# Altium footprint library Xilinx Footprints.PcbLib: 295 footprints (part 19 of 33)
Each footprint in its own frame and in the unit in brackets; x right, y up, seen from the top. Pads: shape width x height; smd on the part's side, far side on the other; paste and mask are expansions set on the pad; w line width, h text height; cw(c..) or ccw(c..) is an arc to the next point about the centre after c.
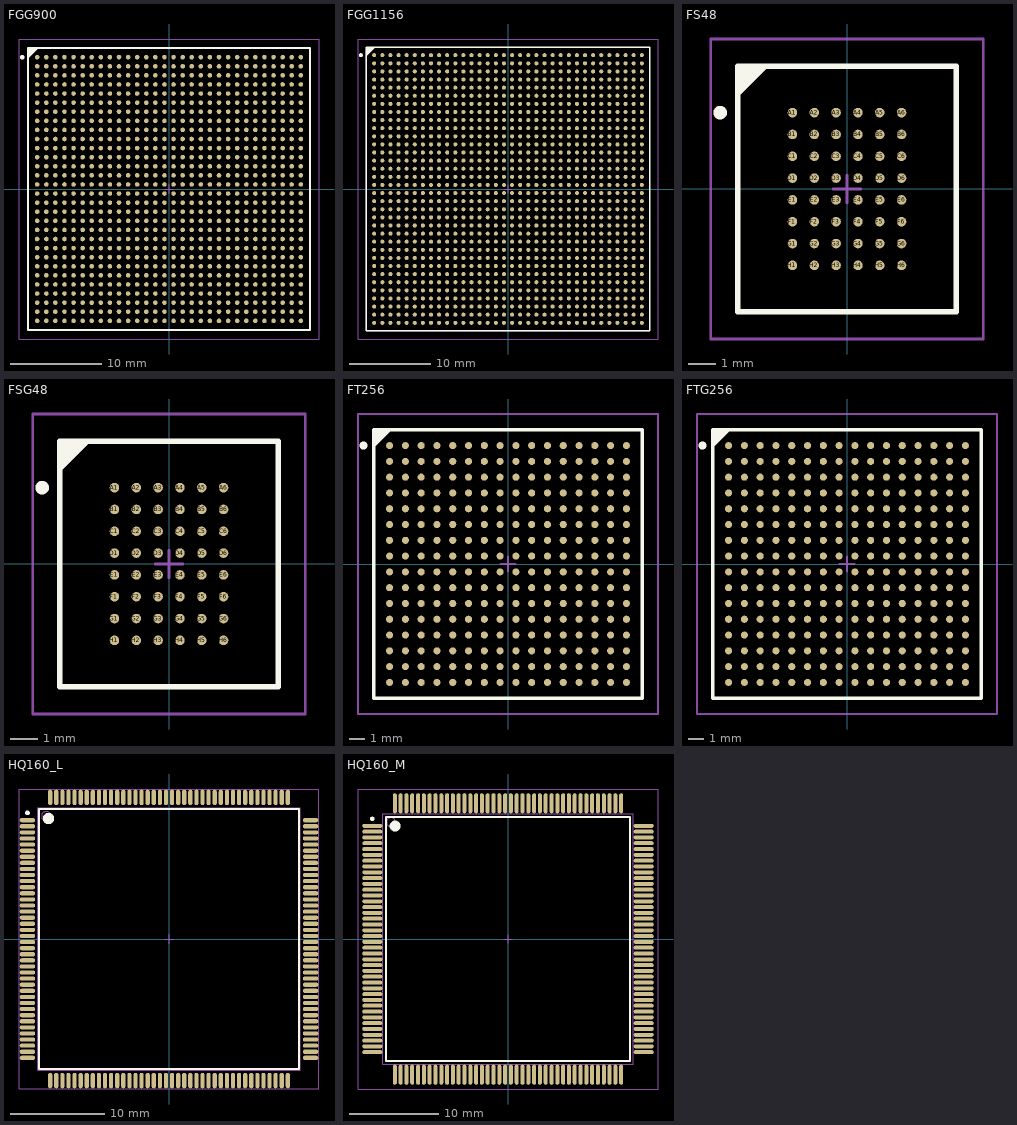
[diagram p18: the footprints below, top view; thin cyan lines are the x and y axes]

## FGG900 [mm] "900-Ball Fine Pitch Ball Grid Array (FGG900) - Pb-Free"
height 2.6
pads (900):
  round 0.5 smd: A1(-14.5,14.5) A2(-13.5,14.5) A3(-12.5,14.5) A4(-11.5,14.5) A5(-10.5,14.5) A6(-9.5,14.5) A7(-8.5,14.5) A8(-7.5,14.5) A9(-6.5,14.5) A10(-5.5,14.5) A11(-4.5,14.5) A12(-3.5,14.5) A13(-2.5,14.5) A14(-1.5,14.5) A15(-0.5,14.5) A16(0.5,14.5) A17(1.5,14.5) A18(2.5,14.5) A19(3.5,14.5) A20(4.5,14.5) A21(5.5,14.5) A22(6.5,14.5) A23(7.5,14.5) A24(8.5,14.5) A25(9.5,14.5) A26(10.5,14.5) A27(11.5,14.5) A28(12.5,14.5) A29(13.5,14.5) A30(14.5,14.5) AA1(-14.5,-5.5) AA2(-13.5,-5.5) AA3(-12.5,-5.5) AA4(-11.5,-5.5) AA5(-10.5,-5.5) AA6(-9.5,-5.5) AA7(-8.5,-5.5) AA8(-7.5,-5.5) AA9(-6.5,-5.5) AA10(-5.5,-5.5) AA11(-4.5,-5.5) AA12(-3.5,-5.5) AA13(-2.5,-5.5) AA14(-1.5,-5.5) AA15(-0.5,-5.5) AA16(0.5,-5.5) AA17(1.5,-5.5) AA18(2.5,-5.5) AA19(3.5,-5.5) AA20(4.5,-5.5) AA21(5.5,-5.5) AA22(6.5,-5.5) AA23(7.5,-5.5) AA24(8.5,-5.5) AA25(9.5,-5.5) AA26(10.5,-5.5) AA27(11.5,-5.5) AA28(12.5,-5.5) AA29(13.5,-5.5) AA30(14.5,-5.5) AB1(-14.5,-6.5) AB2(-13.5,-6.5) AB3(-12.5,-6.5) AB4(-11.5,-6.5) AB5(-10.5,-6.5) AB6(-9.5,-6.5) AB7(-8.5,-6.5) AB8(-7.5,-6.5) AB9(-6.5,-6.5) AB10(-5.5,-6.5) AB11(-4.5,-6.5) AB12(-3.5,-6.5) AB13(-2.5,-6.5) AB14(-1.5,-6.5) AB15(-0.5,-6.5) AB16(0.5,-6.5) AB17(1.5,-6.5) AB18(2.5,-6.5) AB19(3.5,-6.5) AB20(4.5,-6.5) AB21(5.5,-6.5) AB22(6.5,-6.5) AB23(7.5,-6.5) AB24(8.5,-6.5) AB25(9.5,-6.5) AB26(10.5,-6.5) AB27(11.5,-6.5) AB28(12.5,-6.5) AB29(13.5,-6.5) AB30(14.5,-6.5) AC1(-14.5,-7.5) AC2(-13.5,-7.5) AC3(-12.5,-7.5) AC4(-11.5,-7.5) AC5(-10.5,-7.5) AC6(-9.5,-7.5) AC7(-8.5,-7.5) AC8(-7.5,-7.5) AC9(-6.5,-7.5) AC10(-5.5,-7.5) AC11(-4.5,-7.5) AC12(-3.5,-7.5) AC13(-2.5,-7.5) AC14(-1.5,-7.5) AC15(-0.5,-7.5) AC16(0.5,-7.5) AC17(1.5,-7.5) AC18(2.5,-7.5) AC19(3.5,-7.5) AC20(4.5,-7.5) AC21(5.5,-7.5) AC22(6.5,-7.5) AC23(7.5,-7.5) AC24(8.5,-7.5) AC25(9.5,-7.5) AC26(10.5,-7.5) AC27(11.5,-7.5) AC28(12.5,-7.5) AC29(13.5,-7.5) AC30(14.5,-7.5) AD1(-14.5,-8.5) AD2(-13.5,-8.5) AD3(-12.5,-8.5) AD4(-11.5,-8.5) AD5(-10.5,-8.5) AD6(-9.5,-8.5) AD7(-8.5,-8.5) AD8(-7.5,-8.5) AD9(-6.5,-8.5) AD10(-5.5,-8.5) AD11(-4.5,-8.5) AD12(-3.5,-8.5) AD13(-2.5,-8.5) AD14(-1.5,-8.5) AD15(-0.5,-8.5) AD16(0.5,-8.5) AD17(1.5,-8.5) AD18(2.5,-8.5) AD19(3.5,-8.5) AD20(4.5,-8.5) AD21(5.5,-8.5) AD22(6.5,-8.5) AD23(7.5,-8.5) AD24(8.5,-8.5) AD25(9.5,-8.5) AD26(10.5,-8.5) AD27(11.5,-8.5) AD28(12.5,-8.5) AD29(13.5,-8.5) AD30(14.5,-8.5) AE1(-14.5,-9.5) AE2(-13.5,-9.5) AE3(-12.5,-9.5) AE4(-11.5,-9.5) AE5(-10.5,-9.5) AE6(-9.5,-9.5) AE7(-8.5,-9.5) AE8(-7.5,-9.5) AE9(-6.5,-9.5) AE10(-5.5,-9.5) AE11(-4.5,-9.5) AE12(-3.5,-9.5) AE13(-2.5,-9.5) AE14(-1.5,-9.5) AE15(-0.5,-9.5) AE16(0.5,-9.5) AE17(1.5,-9.5) AE18(2.5,-9.5) AE19(3.5,-9.5) AE20(4.5,-9.5) AE21(5.5,-9.5) AE22(6.5,-9.5) AE23(7.5,-9.5) AE24(8.5,-9.5) AE25(9.5,-9.5) AE26(10.5,-9.5) AE27(11.5,-9.5) AE28(12.5,-9.5) AE29(13.5,-9.5) AE30(14.5,-9.5) AF1(-14.5,-10.5) AF2(-13.5,-10.5) AF3(-12.5,-10.5) AF4(-11.5,-10.5) AF5(-10.5,-10.5) AF6(-9.5,-10.5) AF7(-8.5,-10.5) AF8(-7.5,-10.5) AF9(-6.5,-10.5) AF10(-5.5,-10.5) AF11(-4.5,-10.5) AF12(-3.5,-10.5) AF13(-2.5,-10.5) AF14(-1.5,-10.5) AF15(-0.5,-10.5) AF16(0.5,-10.5) AF17(1.5,-10.5) AF18(2.5,-10.5) AF19(3.5,-10.5) AF20(4.5,-10.5) AF21(5.5,-10.5) AF22(6.5,-10.5) AF23(7.5,-10.5) AF24(8.5,-10.5) AF25(9.5,-10.5) AF26(10.5,-10.5) AF27(11.5,-10.5) AF28(12.5,-10.5) AF29(13.5,-10.5) AF30(14.5,-10.5) AG1(-14.5,-11.5) AG2(-13.5,-11.5) AG3(-12.5,-11.5) AG4(-11.5,-11.5) AG5(-10.5,-11.5) AG6(-9.5,-11.5) AG7(-8.5,-11.5) AG8(-7.5,-11.5) AG9(-6.5,-11.5) AG10(-5.5,-11.5) AG11(-4.5,-11.5) AG12(-3.5,-11.5) AG13(-2.5,-11.5) AG14(-1.5,-11.5) AG15(-0.5,-11.5) AG16(0.5,-11.5) AG17(1.5,-11.5) AG18(2.5,-11.5) AG19(3.5,-11.5) AG20(4.5,-11.5) AG21(5.5,-11.5) AG22(6.5,-11.5) AG23(7.5,-11.5) AG24(8.5,-11.5) AG25(9.5,-11.5) AG26(10.5,-11.5) AG27(11.5,-11.5) AG28(12.5,-11.5) AG29(13.5,-11.5) AG30(14.5,-11.5) AH1(-14.5,-12.5) AH2(-13.5,-12.5) AH3(-12.5,-12.5) AH4(-11.5,-12.5) AH5(-10.5,-12.5) AH6(-9.5,-12.5) AH7(-8.5,-12.5) AH8(-7.5,-12.5) AH9(-6.5,-12.5) AH10(-5.5,-12.5) AH11(-4.5,-12.5) AH12(-3.5,-12.5) AH13(-2.5,-12.5) AH14(-1.5,-12.5) AH15(-0.5,-12.5) AH16(0.5,-12.5) AH17(1.5,-12.5) AH18(2.5,-12.5) AH19(3.5,-12.5) AH20(4.5,-12.5) AH21(5.5,-12.5) AH22(6.5,-12.5) AH23(7.5,-12.5) AH24(8.5,-12.5) AH25(9.5,-12.5) AH26(10.5,-12.5) AH27(11.5,-12.5) AH28(12.5,-12.5) AH29(13.5,-12.5) AH30(14.5,-12.5) AJ1(-14.5,-13.5) AJ2(-13.5,-13.5) AJ3(-12.5,-13.5) AJ4(-11.5,-13.5) AJ5(-10.5,-13.5) AJ6(-9.5,-13.5) AJ7(-8.5,-13.5) AJ8(-7.5,-13.5) AJ9(-6.5,-13.5) AJ10(-5.5,-13.5) AJ11(-4.5,-13.5) AJ12(-3.5,-13.5) AJ13(-2.5,-13.5) AJ14(-1.5,-13.5) AJ15(-0.5,-13.5) AJ16(0.5,-13.5) AJ17(1.5,-13.5) AJ18(2.5,-13.5) AJ19(3.5,-13.5) AJ20(4.5,-13.5) AJ21(5.5,-13.5) AJ22(6.5,-13.5) AJ23(7.5,-13.5) AJ24(8.5,-13.5) AJ25(9.5,-13.5) AJ26(10.5,-13.5) AJ27(11.5,-13.5) AJ28(12.5,-13.5) AJ29(13.5,-13.5) AJ30(14.5,-13.5) AK1(-14.5,-14.5) AK2(-13.5,-14.5) AK3(-12.5,-14.5) AK4(-11.5,-14.5) AK5(-10.5,-14.5) AK6(-9.5,-14.5) AK7(-8.5,-14.5) AK8(-7.5,-14.5) AK9(-6.5,-14.5) AK10(-5.5,-14.5) AK11(-4.5,-14.5) AK12(-3.5,-14.5) AK13(-2.5,-14.5) AK14(-1.5,-14.5) AK15(-0.5,-14.5) AK16(0.5,-14.5) AK17(1.5,-14.5) AK18(2.5,-14.5) AK19(3.5,-14.5) AK20(4.5,-14.5) AK21(5.5,-14.5) AK22(6.5,-14.5) AK23(7.5,-14.5) AK24(8.5,-14.5) AK25(9.5,-14.5) AK26(10.5,-14.5) AK27(11.5,-14.5) AK28(12.5,-14.5) AK29(13.5,-14.5) AK30(14.5,-14.5) B1(-14.5,13.5) B2(-13.5,13.5) B3(-12.5,13.5) B4(-11.5,13.5) B5(-10.5,13.5) B6(-9.5,13.5) B7(-8.5,13.5) B8(-7.5,13.5) B9(-6.5,13.5) B10(-5.5,13.5) B11(-4.5,13.5) B12(-3.5,13.5) B13(-2.5,13.5) B14(-1.5,13.5) B15(-0.5,13.5) B16(0.5,13.5) B17(1.5,13.5) B18(2.5,13.5) B19(3.5,13.5) B20(4.5,13.5) B21(5.5,13.5) B22(6.5,13.5) B23(7.5,13.5) B24(8.5,13.5) B25(9.5,13.5) B26(10.5,13.5) B27(11.5,13.5) B28(12.5,13.5) B29(13.5,13.5) B30(14.5,13.5) C1(-14.5,12.5) C2(-13.5,12.5) C3(-12.5,12.5) C4(-11.5,12.5) C5(-10.5,12.5) C6(-9.5,12.5) C7(-8.5,12.5) C8(-7.5,12.5) C9(-6.5,12.5) C10(-5.5,12.5) C11(-4.5,12.5) C12(-3.5,12.5) C13(-2.5,12.5) C14(-1.5,12.5) C15(-0.5,12.5) C16(0.5,12.5) C17(1.5,12.5) C18(2.5,12.5) C19(3.5,12.5) C20(4.5,12.5) C21(5.5,12.5) C22(6.5,12.5) C23(7.5,12.5) C24(8.5,12.5) C25(9.5,12.5) C26(10.5,12.5) C27(11.5,12.5) C28(12.5,12.5) C29(13.5,12.5) C30(14.5,12.5) D1(-14.5,11.5) D2(-13.5,11.5) D3(-12.5,11.5) D4(-11.5,11.5) D5(-10.5,11.5) D6(-9.5,11.5) D7(-8.5,11.5) D8(-7.5,11.5) D9(-6.5,11.5) D10(-5.5,11.5) D11(-4.5,11.5) D12(-3.5,11.5) D13(-2.5,11.5) D14(-1.5,11.5) D15(-0.5,11.5) D16(0.5,11.5) D17(1.5,11.5) D18(2.5,11.5) D19(3.5,11.5) D20(4.5,11.5) D21(5.5,11.5) D22(6.5,11.5) D23(7.5,11.5) D24(8.5,11.5) D25(9.5,11.5) D26(10.5,11.5) D27(11.5,11.5) D28(12.5,11.5) D29(13.5,11.5) D30(14.5,11.5) E1(-14.5,10.5) E2(-13.5,10.5) E3(-12.5,10.5) E4(-11.5,10.5) E5(-10.5,10.5) E6(-9.5,10.5) E7(-8.5,10.5) E8(-7.5,10.5) E9(-6.5,10.5) E10(-5.5,10.5) E11(-4.5,10.5) E12(-3.5,10.5) E13(-2.5,10.5) E14(-1.5,10.5) E15(-0.5,10.5) E16(0.5,10.5) E17(1.5,10.5) E18(2.5,10.5) E19(3.5,10.5) E20(4.5,10.5) E21(5.5,10.5) E22(6.5,10.5) E23(7.5,10.5) E24(8.5,10.5) E25(9.5,10.5) E26(10.5,10.5) E27(11.5,10.5) E28(12.5,10.5) E29(13.5,10.5) E30(14.5,10.5) F1(-14.5,9.5) F2(-13.5,9.5) F3(-12.5,9.5) F4(-11.5,9.5) F5(-10.5,9.5) F6(-9.5,9.5) F7(-8.5,9.5) F8(-7.5,9.5) F9(-6.5,9.5) F10(-5.5,9.5) F11(-4.5,9.5) F12(-3.5,9.5) F13(-2.5,9.5) F14(-1.5,9.5) F15(-0.5,9.5) F16(0.5,9.5) F17(1.5,9.5) F18(2.5,9.5) F19(3.5,9.5) F20(4.5,9.5) F21(5.5,9.5) F22(6.5,9.5) F23(7.5,9.5) F24(8.5,9.5) F25(9.5,9.5) F26(10.5,9.5) F27(11.5,9.5) F28(12.5,9.5) F29(13.5,9.5) F30(14.5,9.5) G1(-14.5,8.5) G2(-13.5,8.5) G3(-12.5,8.5) G4(-11.5,8.5) G5(-10.5,8.5) G6(-9.5,8.5) G7(-8.5,8.5) G8(-7.5,8.5) G9(-6.5,8.5) G10(-5.5,8.5) G11(-4.5,8.5) G12(-3.5,8.5) G13(-2.5,8.5) G14(-1.5,8.5) G15(-0.5,8.5) G16(0.5,8.5) G17(1.5,8.5) G18(2.5,8.5) G19(3.5,8.5) G20(4.5,8.5) G21(5.5,8.5) G22(6.5,8.5) G23(7.5,8.5) G24(8.5,8.5) G25(9.5,8.5) G26(10.5,8.5) G27(11.5,8.5) G28(12.5,8.5) G29(13.5,8.5) G30(14.5,8.5) H1(-14.5,7.5) H2(-13.5,7.5) H3(-12.5,7.5) H4(-11.5,7.5) H5(-10.5,7.5) H6(-9.5,7.5) H7(-8.5,7.5) H8(-7.5,7.5) H9(-6.5,7.5) H10(-5.5,7.5) H11(-4.5,7.5) H12(-3.5,7.5) H13(-2.5,7.5) H14(-1.5,7.5) H15(-0.5,7.5) H16(0.5,7.5) H17(1.5,7.5) H18(2.5,7.5) H19(3.5,7.5) H20(4.5,7.5) H21(5.5,7.5) H22(6.5,7.5) H23(7.5,7.5) H24(8.5,7.5) H25(9.5,7.5) H26(10.5,7.5) H27(11.5,7.5) H28(12.5,7.5) H29(13.5,7.5) H30(14.5,7.5) J1(-14.5,6.5) J2(-13.5,6.5) J3(-12.5,6.5) J4(-11.5,6.5) J5(-10.5,6.5) J6(-9.5,6.5) J7(-8.5,6.5) J8(-7.5,6.5) J9(-6.5,6.5) J10(-5.5,6.5) J11(-4.5,6.5) J12(-3.5,6.5) J13(-2.5,6.5) J14(-1.5,6.5) J15(-0.5,6.5) J16(0.5,6.5) J17(1.5,6.5) J18(2.5,6.5) J19(3.5,6.5) J20(4.5,6.5) J21(5.5,6.5) J22(6.5,6.5) J23(7.5,6.5) J24(8.5,6.5) J25(9.5,6.5) J26(10.5,6.5) J27(11.5,6.5) J28(12.5,6.5) J29(13.5,6.5) J30(14.5,6.5) K1(-14.5,5.5) K2(-13.5,5.5) K3(-12.5,5.5) K4(-11.5,5.5) K5(-10.5,5.5) K6(-9.5,5.5) K7(-8.5,5.5) K8(-7.5,5.5) K9(-6.5,5.5) K10(-5.5,5.5) K11(-4.5,5.5) K12(-3.5,5.5) K13(-2.5,5.5) K14(-1.5,5.5) K15(-0.5,5.5) K16(0.5,5.5) K17(1.5,5.5) K18(2.5,5.5) K19(3.5,5.5) K20(4.5,5.5) K21(5.5,5.5) K22(6.5,5.5) K23(7.5,5.5) K24(8.5,5.5) K25(9.5,5.5) K26(10.5,5.5) K27(11.5,5.5) K28(12.5,5.5) K29(13.5,5.5) K30(14.5,5.5) L1(-14.5,4.5) L2(-13.5,4.5) L3(-12.5,4.5) L4(-11.5,4.5) L5(-10.5,4.5) L6(-9.5,4.5) L7(-8.5,4.5) L8(-7.5,4.5) L9(-6.5,4.5) L10(-5.5,4.5) L11(-4.5,4.5) L12(-3.5,4.5) L13(-2.5,4.5) L14(-1.5,4.5) L15(-0.5,4.5) L16(0.5,4.5) L17(1.5,4.5) L18(2.5,4.5) L19(3.5,4.5) L20(4.5,4.5) L21(5.5,4.5) L22(6.5,4.5) L23(7.5,4.5) L24(8.5,4.5) L25(9.5,4.5) L26(10.5,4.5) L27(11.5,4.5) L28(12.5,4.5) L29(13.5,4.5) L30(14.5,4.5) M1(-14.5,3.5) M2(-13.5,3.5) M3(-12.5,3.5) M4(-11.5,3.5) M5(-10.5,3.5) M6(-9.5,3.5) M7(-8.5,3.5) M8(-7.5,3.5) M9(-6.5,3.5) M10(-5.5,3.5) M11(-4.5,3.5) M12(-3.5,3.5) M13(-2.5,3.5) M14(-1.5,3.5) M15(-0.5,3.5) M16(0.5,3.5) M17(1.5,3.5) M18(2.5,3.5) M19(3.5,3.5) M20(4.5,3.5) M21(5.5,3.5) M22(6.5,3.5) M23(7.5,3.5) M24(8.5,3.5) M25(9.5,3.5) M26(10.5,3.5) M27(11.5,3.5) M28(12.5,3.5) M29(13.5,3.5) M30(14.5,3.5) N1(-14.5,2.5) N2(-13.5,2.5) N3(-12.5,2.5) N4(-11.5,2.5) N5(-10.5,2.5) N6(-9.5,2.5) N7(-8.5,2.5) N8(-7.5,2.5) N9(-6.5,2.5) N10(-5.5,2.5) N11(-4.5,2.5) N12(-3.5,2.5) N13(-2.5,2.5) N14(-1.5,2.5) N15(-0.5,2.5) N16(0.5,2.5) N17(1.5,2.5) N18(2.5,2.5) N19(3.5,2.5) N20(4.5,2.5) N21(5.5,2.5) N22(6.5,2.5) N23(7.5,2.5) N24(8.5,2.5) N25(9.5,2.5) N26(10.5,2.5) N27(11.5,2.5) N28(12.5,2.5) N29(13.5,2.5) N30(14.5,2.5) P1(-14.5,1.5) P2(-13.5,1.5) P3(-12.5,1.5) P4(-11.5,1.5) P5(-10.5,1.5) P6(-9.5,1.5) P7(-8.5,1.5) P8(-7.5,1.5) P9(-6.5,1.5) P10(-5.5,1.5) P11(-4.5,1.5) P12(-3.5,1.5) P13(-2.5,1.5) P14(-1.5,1.5) P15(-0.5,1.5) P16(0.5,1.5) P17(1.5,1.5) P18(2.5,1.5) P19(3.5,1.5) P20(4.5,1.5) P21(5.5,1.5) P22(6.5,1.5) P23(7.5,1.5) P24(8.5,1.5) P25(9.5,1.5) P26(10.5,1.5) P27(11.5,1.5) P28(12.5,1.5) P29(13.5,1.5) P30(14.5,1.5) R1(-14.5,0.5) R2(-13.5,0.5) R3(-12.5,0.5) R4(-11.5,0.5) R5(-10.5,0.5) R6(-9.5,0.5) R7(-8.5,0.5) R8(-7.5,0.5) R9(-6.5,0.5) R10(-5.5,0.5) R11(-4.5,0.5) R12(-3.5,0.5) R13(-2.5,0.5) R14(-1.5,0.5) R15(-0.5,0.5) R16(0.5,0.5) R17(1.5,0.5) R18(2.5,0.5) R19(3.5,0.5) R20(4.5,0.5) R21(5.5,0.5) R22(6.5,0.5) R23(7.5,0.5) R24(8.5,0.5) R25(9.5,0.5) R26(10.5,0.5) R27(11.5,0.5) R28(12.5,0.5) R29(13.5,0.5) R30(14.5,0.5) T1(-14.5,-0.5) T2(-13.5,-0.5) T3(-12.5,-0.5) T4(-11.5,-0.5) T5(-10.5,-0.5) T6(-9.5,-0.5) T7(-8.5,-0.5) T8(-7.5,-0.5) T9(-6.5,-0.5) T10(-5.5,-0.5) T11(-4.5,-0.5) T12(-3.5,-0.5) T13(-2.5,-0.5) T14(-1.5,-0.5) T15(-0.5,-0.5) T16(0.5,-0.5) T17(1.5,-0.5) T18(2.5,-0.5) T19(3.5,-0.5) T20(4.5,-0.5) T21(5.5,-0.5) T22(6.5,-0.5) T23(7.5,-0.5) T24(8.5,-0.5) T25(9.5,-0.5) T26(10.5,-0.5) T27(11.5,-0.5) T28(12.5,-0.5) T29(13.5,-0.5) T30(14.5,-0.5) U1(-14.5,-1.5) U2(-13.5,-1.5) U3(-12.5,-1.5) U4(-11.5,-1.5) U5(-10.5,-1.5) U6(-9.5,-1.5) U7(-8.5,-1.5) U8(-7.5,-1.5) U9(-6.5,-1.5) U10(-5.5,-1.5) U11(-4.5,-1.5) U12(-3.5,-1.5) U13(-2.5,-1.5) U14(-1.5,-1.5) U15(-0.5,-1.5) U16(0.5,-1.5) U17(1.5,-1.5) U18(2.5,-1.5) U19(3.5,-1.5) U20(4.5,-1.5) U21(5.5,-1.5) U22(6.5,-1.5) U23(7.5,-1.5) U24(8.5,-1.5) U25(9.5,-1.5) U26(10.5,-1.5) U27(11.5,-1.5) U28(12.5,-1.5) U29(13.5,-1.5) U30(14.5,-1.5) V1(-14.5,-2.5) V2(-13.5,-2.5) V3(-12.5,-2.5) V4(-11.5,-2.5) V5(-10.5,-2.5) V6(-9.5,-2.5) V7(-8.5,-2.5) V8(-7.5,-2.5) V9(-6.5,-2.5) V10(-5.5,-2.5) V11(-4.5,-2.5) V12(-3.5,-2.5) V13(-2.5,-2.5) V14(-1.5,-2.5) V15(-0.5,-2.5) V16(0.5,-2.5) V17(1.5,-2.5) V18(2.5,-2.5) V19(3.5,-2.5) V20(4.5,-2.5) V21(5.5,-2.5) V22(6.5,-2.5) V23(7.5,-2.5) V24(8.5,-2.5) V25(9.5,-2.5) V26(10.5,-2.5) V27(11.5,-2.5) V28(12.5,-2.5) V29(13.5,-2.5) V30(14.5,-2.5) W1(-14.5,-3.5) W2(-13.5,-3.5) W3(-12.5,-3.5) W4(-11.5,-3.5) W5(-10.5,-3.5) W6(-9.5,-3.5) W7(-8.5,-3.5) W8(-7.5,-3.5) W9(-6.5,-3.5) W10(-5.5,-3.5) W11(-4.5,-3.5) W12(-3.5,-3.5) W13(-2.5,-3.5) W14(-1.5,-3.5) W15(-0.5,-3.5) W16(0.5,-3.5) W17(1.5,-3.5) W18(2.5,-3.5) W19(3.5,-3.5) W20(4.5,-3.5) W21(5.5,-3.5) W22(6.5,-3.5) W23(7.5,-3.5) W24(8.5,-3.5) W25(9.5,-3.5) W26(10.5,-3.5) W27(11.5,-3.5) W28(12.5,-3.5) W29(13.5,-3.5) W30(14.5,-3.5) Y1(-14.5,-4.5) Y2(-13.5,-4.5) Y3(-12.5,-4.5) Y4(-11.5,-4.5) Y5(-10.5,-4.5) Y6(-9.5,-4.5) Y7(-8.5,-4.5) Y8(-7.5,-4.5) Y9(-6.5,-4.5) Y10(-5.5,-4.5) Y11(-4.5,-4.5) Y12(-3.5,-4.5) Y13(-2.5,-4.5) Y14(-1.5,-4.5) Y15(-0.5,-4.5) Y16(0.5,-4.5) Y17(1.5,-4.5) Y18(2.5,-4.5) Y19(3.5,-4.5) Y20(4.5,-4.5) Y21(5.5,-4.5) Y22(6.5,-4.5) Y23(7.5,-4.5) Y24(8.5,-4.5) Y25(9.5,-4.5) Y26(10.5,-4.5) Y27(11.5,-4.5) Y28(12.5,-4.5) Y29(13.5,-4.5) Y30(14.5,-4.5)
Top Overlay:
  circle w0.25: c-16.15,14.5 r0.125
  region: -14.5,15.5 -15.5,14.5 -15.5,15.5
  lines w0.2: -15.5,14.5 -14.5,15.5 ; -15.5,-15.5 15.5,-15.5 15.5,15.5 -15.5,15.5 -15.5,-15.5
Mechanical 13:
  lines w0.1: -15.5,-15.5 15.5,-15.5 15.5,15.5 -15.5,15.5 -15.5,-15.5
Mechanical 15:
  lines w0.1: -0.5,0 0.5,0 ; 0,-0.5 0,0.5 ; -16.5,-16.5 16.5,-16.5 16.5,16.5 -16.5,16.5 -16.5,-16.5
3D body: height 2.6, standoff 0, extent -15.5,-15.5 15.5,15.5

## FGG1156 [mm] "1156-Ball Fine Pitch Plastic Ball Grid Array (FG1156) - Pb-Free"
height 2.6
pads (1156):
  round 0.5 smd: A1(-16.5,16.5) A2(-15.5,16.5) A3(-14.5,16.5) A4(-13.5,16.5) A5(-12.5,16.5) A6(-11.5,16.5) A7(-10.5,16.5) A8(-9.5,16.5) A9(-8.5,16.5) A10(-7.5,16.5) A11(-6.5,16.5) A12(-5.5,16.5) A13(-4.5,16.5) A14(-3.5,16.5) A15(-2.5,16.5) A16(-1.5,16.5) A17(-0.5,16.5) A18(0.5,16.5) A19(1.5,16.5) A20(2.5,16.5) A21(3.5,16.5) A22(4.5,16.5) A23(5.5,16.5) A24(6.5,16.5) A25(7.5,16.5) A26(8.5,16.5) A27(9.5,16.5) A28(10.5,16.5) A29(11.5,16.5) A30(12.5,16.5) A31(13.5,16.5) A32(14.5,16.5) A33(15.5,16.5) A34(16.5,16.5) AA1(-16.5,-3.5) AA2(-15.5,-3.5) AA3(-14.5,-3.5) AA4(-13.5,-3.5) AA5(-12.5,-3.5) AA6(-11.5,-3.5) AA7(-10.5,-3.5) AA8(-9.5,-3.5) AA9(-8.5,-3.5) AA10(-7.5,-3.5) AA11(-6.5,-3.5) AA12(-5.5,-3.5) AA13(-4.5,-3.5) AA14(-3.5,-3.5) AA15(-2.5,-3.5) AA16(-1.5,-3.5) AA17(-0.5,-3.5) AA18(0.5,-3.5) AA19(1.5,-3.5) AA20(2.5,-3.5) AA21(3.5,-3.5) AA22(4.5,-3.5) AA23(5.5,-3.5) AA24(6.5,-3.5) AA25(7.5,-3.5) AA26(8.5,-3.5) AA27(9.5,-3.5) AA28(10.5,-3.5) AA29(11.5,-3.5) AA30(12.5,-3.5) AA31(13.5,-3.5) AA32(14.5,-3.5) AA33(15.5,-3.5) AA34(16.5,-3.5) AB1(-16.5,-4.5) AB2(-15.5,-4.5) AB3(-14.5,-4.5) AB4(-13.5,-4.5) AB5(-12.5,-4.5) AB6(-11.5,-4.5) AB7(-10.5,-4.5) AB8(-9.5,-4.5) AB9(-8.5,-4.5) AB10(-7.5,-4.5) AB11(-6.5,-4.5) AB12(-5.5,-4.5) AB13(-4.5,-4.5) AB14(-3.5,-4.5) AB15(-2.5,-4.5) AB16(-1.5,-4.5) AB17(-0.5,-4.5) AB18(0.5,-4.5) AB19(1.5,-4.5) AB20(2.5,-4.5) AB21(3.5,-4.5) AB22(4.5,-4.5) AB23(5.5,-4.5) AB24(6.5,-4.5) AB25(7.5,-4.5) AB26(8.5,-4.5) AB27(9.5,-4.5) AB28(10.5,-4.5) AB29(11.5,-4.5) AB30(12.5,-4.5) AB31(13.5,-4.5) AB32(14.5,-4.5) AB33(15.5,-4.5) AB34(16.5,-4.5) AC1(-16.5,-5.5) AC2(-15.5,-5.5) AC3(-14.5,-5.5) AC4(-13.5,-5.5) AC5(-12.5,-5.5) AC6(-11.5,-5.5) AC7(-10.5,-5.5) AC8(-9.5,-5.5) AC9(-8.5,-5.5) AC10(-7.5,-5.5) AC11(-6.5,-5.5) AC12(-5.5,-5.5) AC13(-4.5,-5.5) AC14(-3.5,-5.5) AC15(-2.5,-5.5) AC16(-1.5,-5.5) AC17(-0.5,-5.5) AC18(0.5,-5.5) AC19(1.5,-5.5) AC20(2.5,-5.5) AC21(3.5,-5.5) AC22(4.5,-5.5) AC23(5.5,-5.5) AC24(6.5,-5.5) AC25(7.5,-5.5) AC26(8.5,-5.5) AC27(9.5,-5.5) AC28(10.5,-5.5) AC29(11.5,-5.5) AC30(12.5,-5.5) AC31(13.5,-5.5) AC32(14.5,-5.5) AC33(15.5,-5.5) AC34(16.5,-5.5) AD1(-16.5,-6.5) AD2(-15.5,-6.5) AD3(-14.5,-6.5) AD4(-13.5,-6.5) AD5(-12.5,-6.5) AD6(-11.5,-6.5) AD7(-10.5,-6.5) AD8(-9.5,-6.5) AD9(-8.5,-6.5) AD10(-7.5,-6.5) AD11(-6.5,-6.5) AD12(-5.5,-6.5) AD13(-4.5,-6.5) AD14(-3.5,-6.5) AD15(-2.5,-6.5) AD16(-1.5,-6.5) AD17(-0.5,-6.5) AD18(0.5,-6.5) AD19(1.5,-6.5) AD20(2.5,-6.5) AD21(3.5,-6.5) AD22(4.5,-6.5) AD23(5.5,-6.5) AD24(6.5,-6.5) AD25(7.5,-6.5) AD26(8.5,-6.5) AD27(9.5,-6.5) AD28(10.5,-6.5) AD29(11.5,-6.5) AD30(12.5,-6.5) AD31(13.5,-6.5) AD32(14.5,-6.5) AD33(15.5,-6.5) AD34(16.5,-6.5) AE1(-16.5,-7.5) AE2(-15.5,-7.5) AE3(-14.5,-7.5) AE4(-13.5,-7.5) AE5(-12.5,-7.5) AE6(-11.5,-7.5) AE7(-10.5,-7.5) AE8(-9.5,-7.5) AE9(-8.5,-7.5) AE10(-7.5,-7.5) AE11(-6.5,-7.5) AE12(-5.5,-7.5) AE13(-4.5,-7.5) AE14(-3.5,-7.5) AE15(-2.5,-7.5) AE16(-1.5,-7.5) AE17(-0.5,-7.5) AE18(0.5,-7.5) AE19(1.5,-7.5) AE20(2.5,-7.5) AE21(3.5,-7.5) AE22(4.5,-7.5) AE23(5.5,-7.5) AE24(6.5,-7.5) AE25(7.5,-7.5) AE26(8.5,-7.5) AE27(9.5,-7.5) AE28(10.5,-7.5) AE29(11.5,-7.5) AE30(12.5,-7.5) AE31(13.5,-7.5) AE32(14.5,-7.5) AE33(15.5,-7.5) AE34(16.5,-7.5) AF1(-16.5,-8.5) AF2(-15.5,-8.5) AF3(-14.5,-8.5) AF4(-13.5,-8.5) AF5(-12.5,-8.5) AF6(-11.5,-8.5) AF7(-10.5,-8.5) AF8(-9.5,-8.5) AF9(-8.5,-8.5) AF10(-7.5,-8.5) AF11(-6.5,-8.5) AF12(-5.5,-8.5) AF13(-4.5,-8.5) AF14(-3.5,-8.5) AF15(-2.5,-8.5) AF16(-1.5,-8.5) AF17(-0.5,-8.5) AF18(0.5,-8.5) AF19(1.5,-8.5) AF20(2.5,-8.5) AF21(3.5,-8.5) AF22(4.5,-8.5) AF23(5.5,-8.5) AF24(6.5,-8.5) AF25(7.5,-8.5) AF26(8.5,-8.5) AF27(9.5,-8.5) AF28(10.5,-8.5) AF29(11.5,-8.5) AF30(12.5,-8.5) AF31(13.5,-8.5) AF32(14.5,-8.5) AF33(15.5,-8.5) AF34(16.5,-8.5) AG1(-16.5,-9.5) AG2(-15.5,-9.5) AG3(-14.5,-9.5) AG4(-13.5,-9.5) AG5(-12.5,-9.5) AG6(-11.5,-9.5) AG7(-10.5,-9.5) AG8(-9.5,-9.5) AG9(-8.5,-9.5) AG10(-7.5,-9.5) AG11(-6.5,-9.5) AG12(-5.5,-9.5) AG13(-4.5,-9.5) AG14(-3.5,-9.5) AG15(-2.5,-9.5) AG16(-1.5,-9.5) AG17(-0.5,-9.5) AG18(0.5,-9.5) AG19(1.5,-9.5) AG20(2.5,-9.5) AG21(3.5,-9.5) AG22(4.5,-9.5) AG23(5.5,-9.5) AG24(6.5,-9.5) AG25(7.5,-9.5) AG26(8.5,-9.5) AG27(9.5,-9.5) AG28(10.5,-9.5) AG29(11.5,-9.5) AG30(12.5,-9.5) AG31(13.5,-9.5) AG32(14.5,-9.5) AG33(15.5,-9.5) AG34(16.5,-9.5) AH1(-16.5,-10.5) AH2(-15.5,-10.5) AH3(-14.5,-10.5) AH4(-13.5,-10.5) AH5(-12.5,-10.5) AH6(-11.5,-10.5) AH7(-10.5,-10.5) AH8(-9.5,-10.5) AH9(-8.5,-10.5) AH10(-7.5,-10.5) AH11(-6.5,-10.5) AH12(-5.5,-10.5) AH13(-4.5,-10.5) AH14(-3.5,-10.5) AH15(-2.5,-10.5) AH16(-1.5,-10.5) AH17(-0.5,-10.5) AH18(0.5,-10.5) AH19(1.5,-10.5) AH20(2.5,-10.5) AH21(3.5,-10.5) AH22(4.5,-10.5) AH23(5.5,-10.5) AH24(6.5,-10.5) AH25(7.5,-10.5) AH26(8.5,-10.5) AH27(9.5,-10.5) AH28(10.5,-10.5) AH29(11.5,-10.5) AH30(12.5,-10.5) AH31(13.5,-10.5) AH32(14.5,-10.5) AH33(15.5,-10.5) AH34(16.5,-10.5) AJ1(-16.5,-11.5) AJ2(-15.5,-11.5) AJ3(-14.5,-11.5) AJ4(-13.5,-11.5) AJ5(-12.5,-11.5) AJ6(-11.5,-11.5) AJ7(-10.5,-11.5) AJ8(-9.5,-11.5) AJ9(-8.5,-11.5) AJ10(-7.5,-11.5) AJ11(-6.5,-11.5) AJ12(-5.5,-11.5) AJ13(-4.5,-11.5) AJ14(-3.5,-11.5) AJ15(-2.5,-11.5) AJ16(-1.5,-11.5) AJ17(-0.5,-11.5) AJ18(0.5,-11.5) AJ19(1.5,-11.5) AJ20(2.5,-11.5) AJ21(3.5,-11.5) AJ22(4.5,-11.5) AJ23(5.5,-11.5) AJ24(6.5,-11.5) AJ25(7.5,-11.5) AJ26(8.5,-11.5) AJ27(9.5,-11.5) AJ28(10.5,-11.5) AJ29(11.5,-11.5) AJ30(12.5,-11.5) AJ31(13.5,-11.5) AJ32(14.5,-11.5) AJ33(15.5,-11.5) AJ34(16.5,-11.5) AK1(-16.5,-12.5) AK2(-15.5,-12.5) AK3(-14.5,-12.5) AK4(-13.5,-12.5) AK5(-12.5,-12.5) AK6(-11.5,-12.5) AK7(-10.5,-12.5) AK8(-9.5,-12.5) AK9(-8.5,-12.5) AK10(-7.5,-12.5) AK11(-6.5,-12.5) AK12(-5.5,-12.5) AK13(-4.5,-12.5) AK14(-3.5,-12.5) AK15(-2.5,-12.5) AK16(-1.5,-12.5) AK17(-0.5,-12.5) AK18(0.5,-12.5) AK19(1.5,-12.5) AK20(2.5,-12.5) AK21(3.5,-12.5) AK22(4.5,-12.5) AK23(5.5,-12.5) AK24(6.5,-12.5) AK25(7.5,-12.5) AK26(8.5,-12.5) AK27(9.5,-12.5) AK28(10.5,-12.5) AK29(11.5,-12.5) AK30(12.5,-12.5) AK31(13.5,-12.5) AK32(14.5,-12.5) AK33(15.5,-12.5) AK34(16.5,-12.5) AL1(-16.5,-13.5) AL2(-15.5,-13.5) AL3(-14.5,-13.5) AL4(-13.5,-13.5) AL5(-12.5,-13.5) AL6(-11.5,-13.5) AL7(-10.5,-13.5) AL8(-9.5,-13.5) AL9(-8.5,-13.5) AL10(-7.5,-13.5) AL11(-6.5,-13.5) AL12(-5.5,-13.5) AL13(-4.5,-13.5) AL14(-3.5,-13.5) AL15(-2.5,-13.5) AL16(-1.5,-13.5) AL17(-0.5,-13.5) AL18(0.5,-13.5) AL19(1.5,-13.5) AL20(2.5,-13.5) AL21(3.5,-13.5) AL22(4.5,-13.5) AL23(5.5,-13.5) AL24(6.5,-13.5) AL25(7.5,-13.5) AL26(8.5,-13.5) AL27(9.5,-13.5) AL28(10.5,-13.5) AL29(11.5,-13.5) AL30(12.5,-13.5) AL31(13.5,-13.5) AL32(14.5,-13.5) AL33(15.5,-13.5) AL34(16.5,-13.5) AM1(-16.5,-14.5) AM2(-15.5,-14.5) AM3(-14.5,-14.5) AM4(-13.5,-14.5) AM5(-12.5,-14.5) AM6(-11.5,-14.5) AM7(-10.5,-14.5) AM8(-9.5,-14.5) AM9(-8.5,-14.5) AM10(-7.5,-14.5) AM11(-6.5,-14.5) AM12(-5.5,-14.5) AM13(-4.5,-14.5) AM14(-3.5,-14.5) AM15(-2.5,-14.5) AM16(-1.5,-14.5) AM17(-0.5,-14.5) AM18(0.5,-14.5) AM19(1.5,-14.5) AM20(2.5,-14.5) AM21(3.5,-14.5) AM22(4.5,-14.5) AM23(5.5,-14.5) AM24(6.5,-14.5) AM25(7.5,-14.5) AM26(8.5,-14.5) AM27(9.5,-14.5) AM28(10.5,-14.5) AM29(11.5,-14.5) AM30(12.5,-14.5) AM31(13.5,-14.5) AM32(14.5,-14.5) AM33(15.5,-14.5) AM34(16.5,-14.5) AN1(-16.5,-15.5) AN2(-15.5,-15.5) AN3(-14.5,-15.5) AN4(-13.5,-15.5) AN5(-12.5,-15.5) AN6(-11.5,-15.5) AN7(-10.5,-15.5) AN8(-9.5,-15.5) AN9(-8.5,-15.5) AN10(-7.5,-15.5) AN11(-6.5,-15.5) AN12(-5.5,-15.5) AN13(-4.5,-15.5) AN14(-3.5,-15.5) AN15(-2.5,-15.5) AN16(-1.5,-15.5) AN17(-0.5,-15.5) AN18(0.5,-15.5) AN19(1.5,-15.5) AN20(2.5,-15.5) AN21(3.5,-15.5) AN22(4.5,-15.5) AN23(5.5,-15.5) AN24(6.5,-15.5) AN25(7.5,-15.5) AN26(8.5,-15.5) AN27(9.5,-15.5) AN28(10.5,-15.5) AN29(11.5,-15.5) AN30(12.5,-15.5) AN31(13.5,-15.5) AN32(14.5,-15.5) AN33(15.5,-15.5) AN34(16.5,-15.5) AP1(-16.5,-16.5) AP2(-15.5,-16.5) AP3(-14.5,-16.5) AP4(-13.5,-16.5) AP5(-12.5,-16.5) AP6(-11.5,-16.5) AP7(-10.5,-16.5) AP8(-9.5,-16.5) AP9(-8.5,-16.5) AP10(-7.5,-16.5) AP11(-6.5,-16.5) AP12(-5.5,-16.5) AP13(-4.5,-16.5) AP14(-3.5,-16.5) AP15(-2.5,-16.5) AP16(-1.5,-16.5) AP17(-0.5,-16.5) AP18(0.5,-16.5) AP19(1.5,-16.5) AP20(2.5,-16.5) AP21(3.5,-16.5) AP22(4.5,-16.5) AP23(5.5,-16.5) AP24(6.5,-16.5) AP25(7.5,-16.5) AP26(8.5,-16.5) AP27(9.5,-16.5) AP28(10.5,-16.5) AP29(11.5,-16.5) AP30(12.5,-16.5) AP31(13.5,-16.5) AP32(14.5,-16.5) AP33(15.5,-16.5) AP34(16.5,-16.5) B1(-16.5,15.5) B2(-15.5,15.5) B3(-14.5,15.5) B4(-13.5,15.5) B5(-12.5,15.5) B6(-11.5,15.5) B7(-10.5,15.5) B8(-9.5,15.5) B9(-8.5,15.5) B10(-7.5,15.5) B11(-6.5,15.5) B12(-5.5,15.5) B13(-4.5,15.5) B14(-3.5,15.5) B15(-2.5,15.5) B16(-1.5,15.5) B17(-0.5,15.5) B18(0.5,15.5) B19(1.5,15.5) B20(2.5,15.5) B21(3.5,15.5) B22(4.5,15.5) B23(5.5,15.5) B24(6.5,15.5) B25(7.5,15.5) B26(8.5,15.5) B27(9.5,15.5) B28(10.5,15.5) B29(11.5,15.5) B30(12.5,15.5) B31(13.5,15.5) B32(14.5,15.5) B33(15.5,15.5) B34(16.5,15.5) C1(-16.5,14.5) C2(-15.5,14.5) C3(-14.5,14.5) C4(-13.5,14.5) C5(-12.5,14.5) C6(-11.5,14.5) C7(-10.5,14.5) C8(-9.5,14.5) C9(-8.5,14.5) C10(-7.5,14.5) C11(-6.5,14.5) C12(-5.5,14.5) C13(-4.5,14.5) C14(-3.5,14.5) C15(-2.5,14.5) C16(-1.5,14.5) C17(-0.5,14.5) C18(0.5,14.5) C19(1.5,14.5) C20(2.5,14.5) C21(3.5,14.5) C22(4.5,14.5) C23(5.5,14.5) C24(6.5,14.5) C25(7.5,14.5) C26(8.5,14.5) C27(9.5,14.5) C28(10.5,14.5) C29(11.5,14.5) C30(12.5,14.5) C31(13.5,14.5) C32(14.5,14.5) C33(15.5,14.5) C34(16.5,14.5) D1(-16.5,13.5) D2(-15.5,13.5) D3(-14.5,13.5) D4(-13.5,13.5) D5(-12.5,13.5) D6(-11.5,13.5) D7(-10.5,13.5) D8(-9.5,13.5) D9(-8.5,13.5) D10(-7.5,13.5) D11(-6.5,13.5) D12(-5.5,13.5) D13(-4.5,13.5) D14(-3.5,13.5) D15(-2.5,13.5) D16(-1.5,13.5) D17(-0.5,13.5) D18(0.5,13.5) D19(1.5,13.5) D20(2.5,13.5) D21(3.5,13.5) D22(4.5,13.5) D23(5.5,13.5) D24(6.5,13.5) D25(7.5,13.5) D26(8.5,13.5) D27(9.5,13.5) D28(10.5,13.5) D29(11.5,13.5) D30(12.5,13.5) D31(13.5,13.5) D32(14.5,13.5) D33(15.5,13.5) D34(16.5,13.5) E1(-16.5,12.5) E2(-15.5,12.5) E3(-14.5,12.5) E4(-13.5,12.5) E5(-12.5,12.5) E6(-11.5,12.5) E7(-10.5,12.5) E8(-9.5,12.5) E9(-8.5,12.5) E10(-7.5,12.5) E11(-6.5,12.5) E12(-5.5,12.5) E13(-4.5,12.5) E14(-3.5,12.5) E15(-2.5,12.5) E16(-1.5,12.5) E17(-0.5,12.5) E18(0.5,12.5) E19(1.5,12.5) E20(2.5,12.5) E21(3.5,12.5) E22(4.5,12.5) E23(5.5,12.5) E24(6.5,12.5) E25(7.5,12.5) E26(8.5,12.5) E27(9.5,12.5) E28(10.5,12.5) E29(11.5,12.5) E30(12.5,12.5) E31(13.5,12.5) E32(14.5,12.5) E33(15.5,12.5) E34(16.5,12.5) F1(-16.5,11.5) F2(-15.5,11.5) F3(-14.5,11.5) F4(-13.5,11.5) F5(-12.5,11.5) F6(-11.5,11.5) F7(-10.5,11.5) F8(-9.5,11.5) F9(-8.5,11.5) F10(-7.5,11.5) F11(-6.5,11.5) F12(-5.5,11.5) F13(-4.5,11.5) F14(-3.5,11.5) F15(-2.5,11.5) F16(-1.5,11.5) F17(-0.5,11.5) F18(0.5,11.5) F19(1.5,11.5) F20(2.5,11.5) F21(3.5,11.5) F22(4.5,11.5) F23(5.5,11.5) F24(6.5,11.5) F25(7.5,11.5) F26(8.5,11.5) F27(9.5,11.5) F28(10.5,11.5) F29(11.5,11.5) F30(12.5,11.5) F31(13.5,11.5) F32(14.5,11.5) F33(15.5,11.5) F34(16.5,11.5) G1(-16.5,10.5) G2(-15.5,10.5) G3(-14.5,10.5) G4(-13.5,10.5) G5(-12.5,10.5) G6(-11.5,10.5) G7(-10.5,10.5) G8(-9.5,10.5) G9(-8.5,10.5) G10(-7.5,10.5) G11(-6.5,10.5) G12(-5.5,10.5) G13(-4.5,10.5) G14(-3.5,10.5) G15(-2.5,10.5) G16(-1.5,10.5) G17(-0.5,10.5) G18(0.5,10.5) G19(1.5,10.5) G20(2.5,10.5) G21(3.5,10.5) G22(4.5,10.5) G23(5.5,10.5) G24(6.5,10.5) G25(7.5,10.5) G26(8.5,10.5) G27(9.5,10.5) G28(10.5,10.5) G29(11.5,10.5) G30(12.5,10.5) G31(13.5,10.5) G32(14.5,10.5) G33(15.5,10.5) G34(16.5,10.5) H1(-16.5,9.5) H2(-15.5,9.5) H3(-14.5,9.5) H4(-13.5,9.5) H5(-12.5,9.5) H6(-11.5,9.5) H7(-10.5,9.5) H8(-9.5,9.5) H9(-8.5,9.5) H10(-7.5,9.5) H11(-6.5,9.5) H12(-5.5,9.5) H13(-4.5,9.5) H14(-3.5,9.5) H15(-2.5,9.5) H16(-1.5,9.5) H17(-0.5,9.5) H18(0.5,9.5) H19(1.5,9.5) H20(2.5,9.5) H21(3.5,9.5) H22(4.5,9.5) H23(5.5,9.5) H24(6.5,9.5) H25(7.5,9.5) H26(8.5,9.5) H27(9.5,9.5) H28(10.5,9.5) H29(11.5,9.5) H30(12.5,9.5) H31(13.5,9.5) H32(14.5,9.5) H33(15.5,9.5) H34(16.5,9.5) J1(-16.5,8.5) J2(-15.5,8.5) J3(-14.5,8.5) J4(-13.5,8.5) J5(-12.5,8.5) J6(-11.5,8.5) J7(-10.5,8.5) J8(-9.5,8.5) J9(-8.5,8.5) J10(-7.5,8.5) J11(-6.5,8.5) J12(-5.5,8.5) J13(-4.5,8.5) J14(-3.5,8.5) J15(-2.5,8.5) J16(-1.5,8.5) J17(-0.5,8.5) J18(0.5,8.5) J19(1.5,8.5) J20(2.5,8.5) J21(3.5,8.5) J22(4.5,8.5) J23(5.5,8.5) J24(6.5,8.5) J25(7.5,8.5) J26(8.5,8.5) J27(9.5,8.5) J28(10.5,8.5) J29(11.5,8.5) J30(12.5,8.5) J31(13.5,8.5) J32(14.5,8.5) J33(15.5,8.5) J34(16.5,8.5) K1(-16.5,7.5) K2(-15.5,7.5) K3(-14.5,7.5) K4(-13.5,7.5) K5(-12.5,7.5) K6(-11.5,7.5) K7(-10.5,7.5) K8(-9.5,7.5) K9(-8.5,7.5) K10(-7.5,7.5) K11(-6.5,7.5) K12(-5.5,7.5) K13(-4.5,7.5) K14(-3.5,7.5) K15(-2.5,7.5) K16(-1.5,7.5) K17(-0.5,7.5) K18(0.5,7.5) K19(1.5,7.5) K20(2.5,7.5) K21(3.5,7.5) K22(4.5,7.5) K23(5.5,7.5) K24(6.5,7.5) K25(7.5,7.5) K26(8.5,7.5) K27(9.5,7.5) K28(10.5,7.5) K29(11.5,7.5) K30(12.5,7.5) K31(13.5,7.5) K32(14.5,7.5) K33(15.5,7.5) K34(16.5,7.5) L1(-16.5,6.5) L2(-15.5,6.5) L3(-14.5,6.5) L4(-13.5,6.5) L5(-12.5,6.5) L6(-11.5,6.5) L7(-10.5,6.5) L8(-9.5,6.5) L9(-8.5,6.5) L10(-7.5,6.5) L11(-6.5,6.5) L12(-5.5,6.5) L13(-4.5,6.5) L14(-3.5,6.5) L15(-2.5,6.5) L16(-1.5,6.5) L17(-0.5,6.5) L18(0.5,6.5) L19(1.5,6.5) L20(2.5,6.5) L21(3.5,6.5) L22(4.5,6.5) L23(5.5,6.5) L24(6.5,6.5) L25(7.5,6.5) L26(8.5,6.5) L27(9.5,6.5) L28(10.5,6.5) L29(11.5,6.5) L30(12.5,6.5) L31(13.5,6.5) L32(14.5,6.5) L33(15.5,6.5) L34(16.5,6.5) M1(-16.5,5.5) M2(-15.5,5.5) M3(-14.5,5.5) M4(-13.5,5.5) M5(-12.5,5.5) M6(-11.5,5.5) M7(-10.5,5.5) M8(-9.5,5.5) M9(-8.5,5.5) M10(-7.5,5.5) M11(-6.5,5.5) M12(-5.5,5.5) M13(-4.5,5.5) M14(-3.5,5.5) M15(-2.5,5.5) M16(-1.5,5.5) M17(-0.5,5.5) M18(0.5,5.5) M19(1.5,5.5) M20(2.5,5.5) M21(3.5,5.5) M22(4.5,5.5) M23(5.5,5.5) M24(6.5,5.5) M25(7.5,5.5) M26(8.5,5.5) M27(9.5,5.5) M28(10.5,5.5) M29(11.5,5.5) M30(12.5,5.5) M31(13.5,5.5) M32(14.5,5.5) M33(15.5,5.5) M34(16.5,5.5) N1(-16.5,4.5) N2(-15.5,4.5) N3(-14.5,4.5) N4(-13.5,4.5) N5(-12.5,4.5) N6(-11.5,4.5) N7(-10.5,4.5) N8(-9.5,4.5) N9(-8.5,4.5) N10(-7.5,4.5) N11(-6.5,4.5) N12(-5.5,4.5) N13(-4.5,4.5) N14(-3.5,4.5) N15(-2.5,4.5) N16(-1.5,4.5) N17(-0.5,4.5) N18(0.5,4.5) N19(1.5,4.5) N20(2.5,4.5) N21(3.5,4.5) N22(4.5,4.5) N23(5.5,4.5) N24(6.5,4.5) N25(7.5,4.5) N26(8.5,4.5) N27(9.5,4.5) N28(10.5,4.5) N29(11.5,4.5) N30(12.5,4.5) N31(13.5,4.5) N32(14.5,4.5) N33(15.5,4.5) N34(16.5,4.5) P1(-16.5,3.5) P2(-15.5,3.5) P3(-14.5,3.5) P4(-13.5,3.5) P5(-12.5,3.5) P6(-11.5,3.5) P7(-10.5,3.5) P8(-9.5,3.5) P9(-8.5,3.5) P10(-7.5,3.5) P11(-6.5,3.5) P12(-5.5,3.5) P13(-4.5,3.5) P14(-3.5,3.5) P15(-2.5,3.5) P16(-1.5,3.5) P17(-0.5,3.5) P18(0.5,3.5) P19(1.5,3.5) P20(2.5,3.5) P21(3.5,3.5) P22(4.5,3.5) P23(5.5,3.5) P24(6.5,3.5) P25(7.5,3.5) P26(8.5,3.5) P27(9.5,3.5) P28(10.5,3.5) P29(11.5,3.5) P30(12.5,3.5) P31(13.5,3.5) P32(14.5,3.5) P33(15.5,3.5) P34(16.5,3.5) R1(-16.5,2.5) R2(-15.5,2.5) R3(-14.5,2.5) R4(-13.5,2.5) R5(-12.5,2.5) R6(-11.5,2.5) R7(-10.5,2.5) R8(-9.5,2.5) R9(-8.5,2.5) R10(-7.5,2.5) R11(-6.5,2.5) R12(-5.5,2.5) R13(-4.5,2.5) R14(-3.5,2.5) R15(-2.5,2.5) R16(-1.5,2.5) R17(-0.5,2.5) R18(0.5,2.5) R19(1.5,2.5) R20(2.5,2.5) R21(3.5,2.5) R22(4.5,2.5) R23(5.5,2.5) R24(6.5,2.5) R25(7.5,2.5) R26(8.5,2.5) R27(9.5,2.5) R28(10.5,2.5) R29(11.5,2.5) R30(12.5,2.5) R31(13.5,2.5) R32(14.5,2.5) R33(15.5,2.5) R34(16.5,2.5) T1(-16.5,1.5) T2(-15.5,1.5) T3(-14.5,1.5) T4(-13.5,1.5) T5(-12.5,1.5) T6(-11.5,1.5) T7(-10.5,1.5) T8(-9.5,1.5) T9(-8.5,1.5) T10(-7.5,1.5) T11(-6.5,1.5) T12(-5.5,1.5) T13(-4.5,1.5) T14(-3.5,1.5) T15(-2.5,1.5) T16(-1.5,1.5) T17(-0.5,1.5) T18(0.5,1.5) T19(1.5,1.5) T20(2.5,1.5) T21(3.5,1.5) T22(4.5,1.5) T23(5.5,1.5) T24(6.5,1.5) T25(7.5,1.5) T26(8.5,1.5) T27(9.5,1.5) T28(10.5,1.5) T29(11.5,1.5) T30(12.5,1.5) T31(13.5,1.5) T32(14.5,1.5) T33(15.5,1.5) T34(16.5,1.5) U1(-16.5,0.5) U2(-15.5,0.5) U3(-14.5,0.5) U4(-13.5,0.5) U5(-12.5,0.5) U6(-11.5,0.5) U7(-10.5,0.5) U8(-9.5,0.5) U9(-8.5,0.5) U10(-7.5,0.5) U11(-6.5,0.5) U12(-5.5,0.5) U13(-4.5,0.5) U14(-3.5,0.5) U15(-2.5,0.5) U16(-1.5,0.5) U17(-0.5,0.5) U18(0.5,0.5) U19(1.5,0.5) U20(2.5,0.5) U21(3.5,0.5) U22(4.5,0.5) U23(5.5,0.5) U24(6.5,0.5) U25(7.5,0.5) U26(8.5,0.5) U27(9.5,0.5) U28(10.5,0.5) U29(11.5,0.5) U30(12.5,0.5) U31(13.5,0.5) U32(14.5,0.5) U33(15.5,0.5) U34(16.5,0.5) V1(-16.5,-0.5) V2(-15.5,-0.5) V3(-14.5,-0.5) V4(-13.5,-0.5) V5(-12.5,-0.5) V6(-11.5,-0.5) V7(-10.5,-0.5) V8(-9.5,-0.5) V9(-8.5,-0.5) V10(-7.5,-0.5) V11(-6.5,-0.5) V12(-5.5,-0.5) V13(-4.5,-0.5) V14(-3.5,-0.5) V15(-2.5,-0.5) V16(-1.5,-0.5) V17(-0.5,-0.5) V18(0.5,-0.5) V19(1.5,-0.5) V20(2.5,-0.5) V21(3.5,-0.5) V22(4.5,-0.5) V23(5.5,-0.5) V24(6.5,-0.5) V25(7.5,-0.5) V26(8.5,-0.5) V27(9.5,-0.5) V28(10.5,-0.5) V29(11.5,-0.5) V30(12.5,-0.5) V31(13.5,-0.5) V32(14.5,-0.5) V33(15.5,-0.5) V34(16.5,-0.5) W1(-16.5,-1.5) W2(-15.5,-1.5) W3(-14.5,-1.5) W4(-13.5,-1.5) W5(-12.5,-1.5) W6(-11.5,-1.5) W7(-10.5,-1.5) W8(-9.5,-1.5) W9(-8.5,-1.5) W10(-7.5,-1.5) W11(-6.5,-1.5) W12(-5.5,-1.5) W13(-4.5,-1.5) W14(-3.5,-1.5) W15(-2.5,-1.5) W16(-1.5,-1.5) W17(-0.5,-1.5) W18(0.5,-1.5) W19(1.5,-1.5) W20(2.5,-1.5) W21(3.5,-1.5) W22(4.5,-1.5) W23(5.5,-1.5) W24(6.5,-1.5) W25(7.5,-1.5) W26(8.5,-1.5) W27(9.5,-1.5) W28(10.5,-1.5) W29(11.5,-1.5) W30(12.5,-1.5) W31(13.5,-1.5) W32(14.5,-1.5) W33(15.5,-1.5) W34(16.5,-1.5) Y1(-16.5,-2.5) Y2(-15.5,-2.5) Y3(-14.5,-2.5) Y4(-13.5,-2.5) Y5(-12.5,-2.5) Y6(-11.5,-2.5) Y7(-10.5,-2.5) Y8(-9.5,-2.5) Y9(-8.5,-2.5) Y10(-7.5,-2.5) Y11(-6.5,-2.5) Y12(-5.5,-2.5) Y13(-4.5,-2.5) Y14(-3.5,-2.5) Y15(-2.5,-2.5) Y16(-1.5,-2.5) Y17(-0.5,-2.5) Y18(0.5,-2.5) Y19(1.5,-2.5) Y20(2.5,-2.5) Y21(3.5,-2.5) Y22(4.5,-2.5) Y23(5.5,-2.5) Y24(6.5,-2.5) Y25(7.5,-2.5) Y26(8.5,-2.5) Y27(9.5,-2.5) Y28(10.5,-2.5) Y29(11.5,-2.5) Y30(12.5,-2.5) Y31(13.5,-2.5) Y32(14.5,-2.5) Y33(15.5,-2.5) Y34(16.5,-2.5)
Top Overlay:
  circle w0.25: c-18.15,16.5 r0.125
  region: -16.5,17.5 -17.5,16.5 -17.5,17.5
  lines w0.2: -17.5,16.5 -16.5,17.5 ; -17.5,-17.5 -17.5,17.5 17.5,17.5 17.5,-17.5 -17.5,-17.5
Mechanical 13:
  lines w0.1: -17.5,-17.5 -17.5,17.5 17.5,17.5 17.5,-17.5 -17.5,-17.5
Mechanical 15:
  lines w0.1: -0.5,0 0.5,0 ; 0,-0.5 0,0.5 ; -18.5,-18.5 -18.5,18.5 18.5,18.5 18.5,-18.5 -18.5,-18.5
3D body: height 2.6, standoff 0, extent -17.5,-17.5 17.5,17.5

## FS48 [mm] "48-Ball Chip Scale Ball Grid Array 0.8 mm Pitch (FS48)"
height 1.2
pads (48):
  round 0.35 smd: A1(-2,2.8) A2(-1.2,2.8) A3(-0.4,2.8) A4(0.4,2.8) A5(1.2,2.8) A6(2,2.8) B1(-2,2) B2(-1.2,2) B3(-0.4,2) B4(0.4,2) B5(1.2,2) B6(2,2) C1(-2,1.2) C2(-1.2,1.2) C3(-0.4,1.2) C4(0.4,1.2) C5(1.2,1.2) C6(2,1.2) D1(-2,0.4) D2(-1.2,0.4) D3(-0.4,0.4) D4(0.4,0.4) D5(1.2,0.4) D6(2,0.4) E1(-2,-0.4) E2(-1.2,-0.4) E3(-0.4,-0.4) E4(0.4,-0.4) E5(1.2,-0.4) E6(2,-0.4) F1(-2,-1.2) F2(-1.2,-1.2) F3(-0.4,-1.2) F4(0.4,-1.2) F5(1.2,-1.2) F6(2,-1.2) G1(-2,-2) G2(-1.2,-2) G3(-0.4,-2) G4(0.4,-2) G5(1.2,-2) G6(2,-2) H1(-2,-2.8) H2(-1.2,-2.8) H3(-0.4,-2.8) H4(0.4,-2.8) H5(1.2,-2.8) H6(2,-2.8)
Top Overlay:
  circle w0.25: c-4.65,2.8 r0.125
  region: -3,4.5 -4,3.5 -4,4.5
  lines w0.2: -4,3.5 -3,4.5 ; -4,-4.5 -4,4.5 4,4.5 4,-4.5 -4,-4.5
Mechanical 13:
  lines w0.1: -4,-4.5 -4,4.5 4,4.5 4,-4.5 -4,-4.5
Mechanical 15:
  lines w0.1: -0.5,0 0.5,0 ; 0,-0.5 0,0.5 ; -5,-5.5 -5,5.5 5,5.5 5,-5.5 -5,-5.5
3D body: height 1.2, standoff 0, extent -4,-4.5 4,4.5

## FSG48 [mm] "48-Ball Chip Scale Ball Grid Array 0.8 mm Pitch (FSG48) - Pb-Free"
height 1.2
pads (48):
  round 0.35 smd: A1(-2,2.8) A2(-1.2,2.8) A3(-0.4,2.8) A4(0.4,2.8) A5(1.2,2.8) A6(2,2.8) B1(-2,2) B2(-1.2,2) B3(-0.4,2) B4(0.4,2) B5(1.2,2) B6(2,2) C1(-2,1.2) C2(-1.2,1.2) C3(-0.4,1.2) C4(0.4,1.2) C5(1.2,1.2) C6(2,1.2) D1(-2,0.4) D2(-1.2,0.4) D3(-0.4,0.4) D4(0.4,0.4) D5(1.2,0.4) D6(2,0.4) E1(-2,-0.4) E2(-1.2,-0.4) E3(-0.4,-0.4) E4(0.4,-0.4) E5(1.2,-0.4) E6(2,-0.4) F1(-2,-1.2) F2(-1.2,-1.2) F3(-0.4,-1.2) F4(0.4,-1.2) F5(1.2,-1.2) F6(2,-1.2) G1(-2,-2) G2(-1.2,-2) G3(-0.4,-2) G4(0.4,-2) G5(1.2,-2) G6(2,-2) H1(-2,-2.8) H2(-1.2,-2.8) H3(-0.4,-2.8) H4(0.4,-2.8) H5(1.2,-2.8) H6(2,-2.8)
Top Overlay:
  circle w0.25: c-4.65,2.8 r0.125
  region: -3,4.5 -4,3.5 -4,4.5
  lines w0.2: -4,3.5 -3,4.5 ; -4,-4.5 4,-4.5 4,4.5 -4,4.5 -4,-4.5
Mechanical 13:
  lines w0.1: -4,-4.5 4,-4.5 4,4.5 -4,4.5 -4,-4.5
Mechanical 15:
  lines w0.1: -0.5,0 0.5,0 ; 0,-0.5 0,0.5 ; -5,-5.5 5,-5.5 5,5.5 -5,5.5 -5,-5.5
3D body: height 1.2, standoff 0, extent -4,-4.5 4,4.5

## FT256 [mm] "256-Ball Fine Pitch Thin Ball Grid Array 1.00 mm Pitch (FT256)"
height 1.55
pads (256):
  round 0.45 smd: A1(-7.5,7.5) A2(-6.5,7.5) A3(-5.5,7.5) A4(-4.5,7.5) A5(-3.5,7.5) A6(-2.5,7.5) A7(-1.5,7.5) A8(-0.5,7.5) A9(0.5,7.5) A10(1.5,7.5) A11(2.5,7.5) A12(3.5,7.5) A13(4.5,7.5) A14(5.5,7.5) A15(6.5,7.5) A16(7.5,7.5) B1(-7.5,6.5) B2(-6.5,6.5) B3(-5.5,6.5) B4(-4.5,6.5) B5(-3.5,6.5) B6(-2.5,6.5) B7(-1.5,6.5) B8(-0.5,6.5) B9(0.5,6.5) B10(1.5,6.5) B11(2.5,6.5) B12(3.5,6.5) B13(4.5,6.5) B14(5.5,6.5) B15(6.5,6.5) B16(7.5,6.5) C1(-7.5,5.5) C2(-6.5,5.5) C3(-5.5,5.5) C4(-4.5,5.5) C5(-3.5,5.5) C6(-2.5,5.5) C7(-1.5,5.5) C8(-0.5,5.5) C9(0.5,5.5) C10(1.5,5.5) C11(2.5,5.5) C12(3.5,5.5) C13(4.5,5.5) C14(5.5,5.5) C15(6.5,5.5) C16(7.5,5.5) D1(-7.5,4.5) D2(-6.5,4.5) D3(-5.5,4.5) D4(-4.5,4.5) D5(-3.5,4.5) D6(-2.5,4.5) D7(-1.5,4.5) D8(-0.5,4.5) D9(0.5,4.5) D10(1.5,4.5) D11(2.5,4.5) D12(3.5,4.5) D13(4.5,4.5) D14(5.5,4.5) D15(6.5,4.5) D16(7.5,4.5) E1(-7.5,3.5) E2(-6.5,3.5) E3(-5.5,3.5) E4(-4.5,3.5) E5(-3.5,3.5) E6(-2.5,3.5) E7(-1.5,3.5) E8(-0.5,3.5) E9(0.5,3.5) E10(1.5,3.5) E11(2.5,3.5) E12(3.5,3.5) E13(4.5,3.5) E14(5.5,3.5) E15(6.5,3.5) E16(7.5,3.5) F1(-7.5,2.5) F2(-6.5,2.5) F3(-5.5,2.5) F4(-4.5,2.5) F5(-3.5,2.5) F6(-2.5,2.5) F7(-1.5,2.5) F8(-0.5,2.5) F9(0.5,2.5) F10(1.5,2.5) F11(2.5,2.5) F12(3.5,2.5) F13(4.5,2.5) F14(5.5,2.5) F15(6.5,2.5) F16(7.5,2.5) G1(-7.5,1.5) G2(-6.5,1.5) G3(-5.5,1.5) G4(-4.5,1.5) G5(-3.5,1.5) G6(-2.5,1.5) G7(-1.5,1.5) G8(-0.5,1.5) G9(0.5,1.5) G10(1.5,1.5) G11(2.5,1.5) G12(3.5,1.5) G13(4.5,1.5) G14(5.5,1.5) G15(6.5,1.5) G16(7.5,1.5) H1(-7.5,0.5) H2(-6.5,0.5) H3(-5.5,0.5) H4(-4.5,0.5) H5(-3.5,0.5) H6(-2.5,0.5) H7(-1.5,0.5) H8(-0.5,0.5) H9(0.5,0.5) H10(1.5,0.5) H11(2.5,0.5) H12(3.5,0.5) H13(4.5,0.5) H14(5.5,0.5) H15(6.5,0.5) H16(7.5,0.5) J1(-7.5,-0.5) J2(-6.5,-0.5) J3(-5.5,-0.5) J4(-4.5,-0.5) J5(-3.5,-0.5) J6(-2.5,-0.5) J7(-1.5,-0.5) J8(-0.5,-0.5) J9(0.5,-0.5) J10(1.5,-0.5) J11(2.5,-0.5) J12(3.5,-0.5) J13(4.5,-0.5) J14(5.5,-0.5) J15(6.5,-0.5) J16(7.5,-0.5) K1(-7.5,-1.5) K2(-6.5,-1.5) K3(-5.5,-1.5) K4(-4.5,-1.5) K5(-3.5,-1.5) K6(-2.5,-1.5) K7(-1.5,-1.5) K8(-0.5,-1.5) K9(0.5,-1.5) K10(1.5,-1.5) K11(2.5,-1.5) K12(3.5,-1.5) K13(4.5,-1.5) K14(5.5,-1.5) K15(6.5,-1.5) K16(7.5,-1.5) L1(-7.5,-2.5) L2(-6.5,-2.5) L3(-5.5,-2.5) L4(-4.5,-2.5) L5(-3.5,-2.5) L6(-2.5,-2.5) L7(-1.5,-2.5) L8(-0.5,-2.5) L9(0.5,-2.5) L10(1.5,-2.5) L11(2.5,-2.5) L12(3.5,-2.5) L13(4.5,-2.5) L14(5.5,-2.5) L15(6.5,-2.5) L16(7.5,-2.5) M1(-7.5,-3.5) M2(-6.5,-3.5) M3(-5.5,-3.5) M4(-4.5,-3.5) M5(-3.5,-3.5) M6(-2.5,-3.5) M7(-1.5,-3.5) M8(-0.5,-3.5) M9(0.5,-3.5) M10(1.5,-3.5) M11(2.5,-3.5) M12(3.5,-3.5) M13(4.5,-3.5) M14(5.5,-3.5) M15(6.5,-3.5) M16(7.5,-3.5) N1(-7.5,-4.5) N2(-6.5,-4.5) N3(-5.5,-4.5) N4(-4.5,-4.5) N5(-3.5,-4.5) N6(-2.5,-4.5) N7(-1.5,-4.5) N8(-0.5,-4.5) N9(0.5,-4.5) N10(1.5,-4.5) N11(2.5,-4.5) N12(3.5,-4.5) N13(4.5,-4.5) N14(5.5,-4.5) N15(6.5,-4.5) N16(7.5,-4.5) P1(-7.5,-5.5) P2(-6.5,-5.5) P3(-5.5,-5.5) P4(-4.5,-5.5) P5(-3.5,-5.5) P6(-2.5,-5.5) P7(-1.5,-5.5) P8(-0.5,-5.5) P9(0.5,-5.5) P10(1.5,-5.5) P11(2.5,-5.5) P12(3.5,-5.5) P13(4.5,-5.5) P14(5.5,-5.5) P15(6.5,-5.5) P16(7.5,-5.5) R1(-7.5,-6.5) R2(-6.5,-6.5) R3(-5.5,-6.5) R4(-4.5,-6.5) R5(-3.5,-6.5) R6(-2.5,-6.5) R7(-1.5,-6.5) R8(-0.5,-6.5) R9(0.5,-6.5) R10(1.5,-6.5) R11(2.5,-6.5) R12(3.5,-6.5) R13(4.5,-6.5) R14(5.5,-6.5) R15(6.5,-6.5) R16(7.5,-6.5) T1(-7.5,-7.5) T2(-6.5,-7.5) T3(-5.5,-7.5) T4(-4.5,-7.5) T5(-3.5,-7.5) T6(-2.5,-7.5) T7(-1.5,-7.5) T8(-0.5,-7.5) T9(0.5,-7.5) T10(1.5,-7.5) T11(2.5,-7.5) T12(3.5,-7.5) T13(4.5,-7.5) T14(5.5,-7.5) T15(6.5,-7.5) T16(7.5,-7.5)
Top Overlay:
  circle w0.25: c-9.15,7.5 r0.125
  region: -7.5,8.5 -8.5,7.5 -8.5,8.5
  lines w0.2: -8.5,7.5 -7.5,8.5 ; -8.5,-8.5 -8.5,8.5 8.5,8.5 8.5,-8.5 -8.5,-8.5
Mechanical 13:
  lines w0.1: -8.5,-8.5 -8.5,8.5 8.5,8.5 8.5,-8.5 -8.5,-8.5
Mechanical 15:
  lines w0.1: -0.5,0 0.5,0 ; 0,-0.5 0,0.5 ; -9.5,-9.5 -9.5,9.5 9.5,9.5 9.5,-9.5 -9.5,-9.5
3D body: height 1.55, standoff 0, extent -8.5,-8.5 8.5,8.5

## FTG256 [mm] "256-Ball Fine Pitch Thin Ball Grid Array 1.00 mm Pitch (FTG256) - Pb-Free"
height 1.55
pads (256):
  round 0.45 smd: A1(-7.5,7.5) A2(-6.5,7.5) A3(-5.5,7.5) A4(-4.5,7.5) A5(-3.5,7.5) A6(-2.5,7.5) A7(-1.5,7.5) A8(-0.5,7.5) A9(0.5,7.5) A10(1.5,7.5) A11(2.5,7.5) A12(3.5,7.5) A13(4.5,7.5) A14(5.5,7.5) A15(6.5,7.5) A16(7.5,7.5) B1(-7.5,6.5) B2(-6.5,6.5) B3(-5.5,6.5) B4(-4.5,6.5) B5(-3.5,6.5) B6(-2.5,6.5) B7(-1.5,6.5) B8(-0.5,6.5) B9(0.5,6.5) B10(1.5,6.5) B11(2.5,6.5) B12(3.5,6.5) B13(4.5,6.5) B14(5.5,6.5) B15(6.5,6.5) B16(7.5,6.5) C1(-7.5,5.5) C2(-6.5,5.5) C3(-5.5,5.5) C4(-4.5,5.5) C5(-3.5,5.5) C6(-2.5,5.5) C7(-1.5,5.5) C8(-0.5,5.5) C9(0.5,5.5) C10(1.5,5.5) C11(2.5,5.5) C12(3.5,5.5) C13(4.5,5.5) C14(5.5,5.5) C15(6.5,5.5) C16(7.5,5.5) D1(-7.5,4.5) D2(-6.5,4.5) D3(-5.5,4.5) D4(-4.5,4.5) D5(-3.5,4.5) D6(-2.5,4.5) D7(-1.5,4.5) D8(-0.5,4.5) D9(0.5,4.5) D10(1.5,4.5) D11(2.5,4.5) D12(3.5,4.5) D13(4.5,4.5) D14(5.5,4.5) D15(6.5,4.5) D16(7.5,4.5) E1(-7.5,3.5) E2(-6.5,3.5) E3(-5.5,3.5) E4(-4.5,3.5) E5(-3.5,3.5) E6(-2.5,3.5) E7(-1.5,3.5) E8(-0.5,3.5) E9(0.5,3.5) E10(1.5,3.5) E11(2.5,3.5) E12(3.5,3.5) E13(4.5,3.5) E14(5.5,3.5) E15(6.5,3.5) E16(7.5,3.5) F1(-7.5,2.5) F2(-6.5,2.5) F3(-5.5,2.5) F4(-4.5,2.5) F5(-3.5,2.5) F6(-2.5,2.5) F7(-1.5,2.5) F8(-0.5,2.5) F9(0.5,2.5) F10(1.5,2.5) F11(2.5,2.5) F12(3.5,2.5) F13(4.5,2.5) F14(5.5,2.5) F15(6.5,2.5) F16(7.5,2.5) G1(-7.5,1.5) G2(-6.5,1.5) G3(-5.5,1.5) G4(-4.5,1.5) G5(-3.5,1.5) G6(-2.5,1.5) G7(-1.5,1.5) G8(-0.5,1.5) G9(0.5,1.5) G10(1.5,1.5) G11(2.5,1.5) G12(3.5,1.5) G13(4.5,1.5) G14(5.5,1.5) G15(6.5,1.5) G16(7.5,1.5) H1(-7.5,0.5) H2(-6.5,0.5) H3(-5.5,0.5) H4(-4.5,0.5) H5(-3.5,0.5) H6(-2.5,0.5) H7(-1.5,0.5) H8(-0.5,0.5) H9(0.5,0.5) H10(1.5,0.5) H11(2.5,0.5) H12(3.5,0.5) H13(4.5,0.5) H14(5.5,0.5) H15(6.5,0.5) H16(7.5,0.5) J1(-7.5,-0.5) J2(-6.5,-0.5) J3(-5.5,-0.5) J4(-4.5,-0.5) J5(-3.5,-0.5) J6(-2.5,-0.5) J7(-1.5,-0.5) J8(-0.5,-0.5) J9(0.5,-0.5) J10(1.5,-0.5) J11(2.5,-0.5) J12(3.5,-0.5) J13(4.5,-0.5) J14(5.5,-0.5) J15(6.5,-0.5) J16(7.5,-0.5) K1(-7.5,-1.5) K2(-6.5,-1.5) K3(-5.5,-1.5) K4(-4.5,-1.5) K5(-3.5,-1.5) K6(-2.5,-1.5) K7(-1.5,-1.5) K8(-0.5,-1.5) K9(0.5,-1.5) K10(1.5,-1.5) K11(2.5,-1.5) K12(3.5,-1.5) K13(4.5,-1.5) K14(5.5,-1.5) K15(6.5,-1.5) K16(7.5,-1.5) L1(-7.5,-2.5) L2(-6.5,-2.5) L3(-5.5,-2.5) L4(-4.5,-2.5) L5(-3.5,-2.5) L6(-2.5,-2.5) L7(-1.5,-2.5) L8(-0.5,-2.5) L9(0.5,-2.5) L10(1.5,-2.5) L11(2.5,-2.5) L12(3.5,-2.5) L13(4.5,-2.5) L14(5.5,-2.5) L15(6.5,-2.5) L16(7.5,-2.5) M1(-7.5,-3.5) M2(-6.5,-3.5) M3(-5.5,-3.5) M4(-4.5,-3.5) M5(-3.5,-3.5) M6(-2.5,-3.5) M7(-1.5,-3.5) M8(-0.5,-3.5) M9(0.5,-3.5) M10(1.5,-3.5) M11(2.5,-3.5) M12(3.5,-3.5) M13(4.5,-3.5) M14(5.5,-3.5) M15(6.5,-3.5) M16(7.5,-3.5) N1(-7.5,-4.5) N2(-6.5,-4.5) N3(-5.5,-4.5) N4(-4.5,-4.5) N5(-3.5,-4.5) N6(-2.5,-4.5) N7(-1.5,-4.5) N8(-0.5,-4.5) N9(0.5,-4.5) N10(1.5,-4.5) N11(2.5,-4.5) N12(3.5,-4.5) N13(4.5,-4.5) N14(5.5,-4.5) N15(6.5,-4.5) N16(7.5,-4.5) P1(-7.5,-5.5) P2(-6.5,-5.5) P3(-5.5,-5.5) P4(-4.5,-5.5) P5(-3.5,-5.5) P6(-2.5,-5.5) P7(-1.5,-5.5) P8(-0.5,-5.5) P9(0.5,-5.5) P10(1.5,-5.5) P11(2.5,-5.5) P12(3.5,-5.5) P13(4.5,-5.5) P14(5.5,-5.5) P15(6.5,-5.5) P16(7.5,-5.5) R1(-7.5,-6.5) R2(-6.5,-6.5) R3(-5.5,-6.5) R4(-4.5,-6.5) R5(-3.5,-6.5) R6(-2.5,-6.5) R7(-1.5,-6.5) R8(-0.5,-6.5) R9(0.5,-6.5) R10(1.5,-6.5) R11(2.5,-6.5) R12(3.5,-6.5) R13(4.5,-6.5) R14(5.5,-6.5) R15(6.5,-6.5) R16(7.5,-6.5) T1(-7.5,-7.5) T2(-6.5,-7.5) T3(-5.5,-7.5) T4(-4.5,-7.5) T5(-3.5,-7.5) T6(-2.5,-7.5) T7(-1.5,-7.5) T8(-0.5,-7.5) T9(0.5,-7.5) T10(1.5,-7.5) T11(2.5,-7.5) T12(3.5,-7.5) T13(4.5,-7.5) T14(5.5,-7.5) T15(6.5,-7.5) T16(7.5,-7.5)
Top Overlay:
  circle w0.25: c-9.15,7.5 r0.125
  region: -7.5,8.5 -8.5,7.5 -8.5,8.5
  lines w0.2: -8.5,7.5 -7.5,8.5 ; -8.5,-8.5 -8.5,8.5 8.5,8.5 8.5,-8.5 -8.5,-8.5
Mechanical 13:
  lines w0.1: -8.5,-8.5 -8.5,8.5 8.5,8.5 8.5,-8.5 -8.5,-8.5
Mechanical 15:
  lines w0.1: -0.5,0 0.5,0 ; 0,-0.5 0,0.5 ; -9.5,-9.5 -9.5,9.5 9.5,9.5 9.5,-9.5 -9.5,-9.5
3D body: height 1.55, standoff 0, extent -8.5,-8.5 8.5,8.5

## HQ160_L [mm] "160-Pin Heat Sink Quad Flat Pack (HQ160), IPC High Density"
height 4.1
pads (160):
  oval 1.65x0.45 smd: 1(-15.1,12.675) 2(-15.1,12.025) 3(-15.1,11.375) 4(-15.1,10.725) 5(-15.1,10.075) 6(-15.1,9.425) 7(-15.1,8.775) 8(-15.1,8.125) 9(-15.1,7.475) 10(-15.1,6.825) 11(-15.1,6.175) 12(-15.1,5.525) 13(-15.1,4.875) 14(-15.1,4.225) 15(-15.1,3.575) 16(-15.1,2.925) 17(-15.1,2.275) 18(-15.1,1.625) 19(-15.1,0.975) 20(-15.1,0.325) 21(-15.1,-0.325) 22(-15.1,-0.975) 23(-15.1,-1.625) 24(-15.1,-2.275) 25(-15.1,-2.925) 26(-15.1,-3.575) 27(-15.1,-4.225) 28(-15.1,-4.875) 29(-15.1,-5.525) 30(-15.1,-6.175) 31(-15.1,-6.825) 32(-15.1,-7.475) 33(-15.1,-8.125) 34(-15.1,-8.775) 35(-15.1,-9.425) 36(-15.1,-10.075) 37(-15.1,-10.725) 38(-15.1,-11.375) 39(-15.1,-12.025) 40(-15.1,-12.675) 81(15.1,-12.675) 82(15.1,-12.025) 83(15.1,-11.375) 84(15.1,-10.725) 85(15.1,-10.075) 86(15.1,-9.425) 87(15.1,-8.775) 88(15.1,-8.125) 89(15.1,-7.475) 90(15.1,-6.825) 91(15.1,-6.175) 92(15.1,-5.525) 93(15.1,-4.875) 94(15.1,-4.225) 95(15.1,-3.575) 96(15.1,-2.925) 97(15.1,-2.275) 98(15.1,-1.625) 99(15.1,-0.975) 100(15.1,-0.325) 101(15.1,0.325) 102(15.1,0.975) 103(15.1,1.625) 104(15.1,2.275) 105(15.1,2.925) 106(15.1,3.575) 107(15.1,4.225) 108(15.1,4.875) 109(15.1,5.525) 110(15.1,6.175) 111(15.1,6.825) 112(15.1,7.475) 113(15.1,8.125) 114(15.1,8.775) 115(15.1,9.425) 116(15.1,10.075) 117(15.1,10.725) 118(15.1,11.375) 119(15.1,12.025) 120(15.1,12.675)
  oval 0.45x1.65 smd: 41(-12.675,-15.1) 42(-12.025,-15.1) 43(-11.375,-15.1) 44(-10.725,-15.1) 45(-10.075,-15.1) 46(-9.425,-15.1) 47(-8.775,-15.1) 48(-8.125,-15.1) 49(-7.475,-15.1) 50(-6.825,-15.1) 51(-6.175,-15.1) 52(-5.525,-15.1) 53(-4.875,-15.1) 54(-4.225,-15.1) 55(-3.575,-15.1) 56(-2.925,-15.1) 57(-2.275,-15.1) 58(-1.625,-15.1) 59(-0.975,-15.1) 60(-0.325,-15.1) 61(0.325,-15.1) 62(0.975,-15.1) 63(1.625,-15.1) 64(2.275,-15.1) 65(2.925,-15.1) 66(3.575,-15.1) 67(4.225,-15.1) 68(4.875,-15.1) 69(5.525,-15.1) 70(6.175,-15.1) 71(6.825,-15.1) 72(7.475,-15.1) 73(8.125,-15.1) 74(8.775,-15.1) 75(9.425,-15.1) 76(10.075,-15.1) 77(10.725,-15.1) 78(11.375,-15.1) 79(12.025,-15.1) 80(12.675,-15.1) 121(12.675,15.1) 122(12.025,15.1) 123(11.375,15.1) 124(10.725,15.1) 125(10.075,15.1) 126(9.425,15.1) 127(8.775,15.1) 128(8.125,15.1) 129(7.475,15.1) 130(6.825,15.1) 131(6.175,15.1) 132(5.525,15.1) 133(4.875,15.1) 134(4.225,15.1) 135(3.575,15.1) 136(2.925,15.1) 137(2.275,15.1) 138(1.625,15.1) 139(0.975,15.1) 140(0.325,15.1) 141(-0.325,15.1) 142(-0.975,15.1) 143(-1.625,15.1) 144(-2.275,15.1) 145(-2.925,15.1) 146(-3.575,15.1) 147(-4.225,15.1) 148(-4.875,15.1) 149(-5.525,15.1) 150(-6.175,15.1) 151(-6.825,15.1) 152(-7.475,15.1) 153(-8.125,15.1) 154(-8.775,15.1) 155(-9.425,15.1) 156(-10.075,15.1) 157(-10.725,15.1) 158(-11.375,15.1) 159(-12.025,15.1) 160(-12.675,15.1)
Top Overlay:
  circle w0.6: c-12.85,12.85 r0.3
  circle w0.25: c-15.1,13.45 r0.125
  lines w0.2: -13.85,-13.85 13.85,-13.85 13.85,13.85 -13.85,13.85 -13.85,-13.85
Mechanical 13:
  circle w0.1: c-13.1,13.1 r0.5
  lines w0.1: -14,-14 14,-14 14,14 -14,14 -14,-14
Mechanical 15:
  lines w0.1: -0.5,0 0.5,0 ; 0,-0.5 0,0.5 ; -16,-16 16,-16 16,16 -16,16 -16,-16
3D body: height 4.1, standoff 0, extent -14,-14 14,14

## HQ160_M [mm] "160-Pin Heat Sink Quad Flat Pack (HQ160), IPC Low Density"
height 4.1
pads (160):
  oval 2.25x0.45 smd: 1(-15.2,12.675) 2(-15.2,12.025) 3(-15.2,11.375) 4(-15.2,10.725) 5(-15.2,10.075) 6(-15.2,9.425) 7(-15.2,8.775) 8(-15.2,8.125) 9(-15.2,7.475) 10(-15.2,6.825) 11(-15.2,6.175) 12(-15.2,5.525) 13(-15.2,4.875) 14(-15.2,4.225) 15(-15.2,3.575) 16(-15.2,2.925) 17(-15.2,2.275) 18(-15.2,1.625) 19(-15.2,0.975) 20(-15.2,0.325) 21(-15.2,-0.325) 22(-15.2,-0.975) 23(-15.2,-1.625) 24(-15.2,-2.275) 25(-15.2,-2.925) 26(-15.2,-3.575) 27(-15.2,-4.225) 28(-15.2,-4.875) 29(-15.2,-5.525) 30(-15.2,-6.175) 31(-15.2,-6.825) 32(-15.2,-7.475) 33(-15.2,-8.125) 34(-15.2,-8.775) 35(-15.2,-9.425) 36(-15.2,-10.075) 37(-15.2,-10.725) 38(-15.2,-11.375) 39(-15.2,-12.025) 40(-15.2,-12.675) 81(15.2,-12.675) 82(15.2,-12.025) 83(15.2,-11.375) 84(15.2,-10.725) 85(15.2,-10.075) 86(15.2,-9.425) 87(15.2,-8.775) 88(15.2,-8.125) 89(15.2,-7.475) 90(15.2,-6.825) 91(15.2,-6.175) 92(15.2,-5.525) 93(15.2,-4.875) 94(15.2,-4.225) 95(15.2,-3.575) 96(15.2,-2.925) 97(15.2,-2.275) 98(15.2,-1.625) 99(15.2,-0.975) 100(15.2,-0.325) 101(15.2,0.325) 102(15.2,0.975) 103(15.2,1.625) 104(15.2,2.275) 105(15.2,2.925) 106(15.2,3.575) 107(15.2,4.225) 108(15.2,4.875) 109(15.2,5.525) 110(15.2,6.175) 111(15.2,6.825) 112(15.2,7.475) 113(15.2,8.125) 114(15.2,8.775) 115(15.2,9.425) 116(15.2,10.075) 117(15.2,10.725) 118(15.2,11.375) 119(15.2,12.025) 120(15.2,12.675)
  oval 0.45x2.25 smd: 41(-12.675,-15.2) 42(-12.025,-15.2) 43(-11.375,-15.2) 44(-10.725,-15.2) 45(-10.075,-15.2) 46(-9.425,-15.2) 47(-8.775,-15.2) 48(-8.125,-15.2) 49(-7.475,-15.2) 50(-6.825,-15.2) 51(-6.175,-15.2) 52(-5.525,-15.2) 53(-4.875,-15.2) 54(-4.225,-15.2) 55(-3.575,-15.2) 56(-2.925,-15.2) 57(-2.275,-15.2) 58(-1.625,-15.2) 59(-0.975,-15.2) 60(-0.325,-15.2) 61(0.325,-15.2) 62(0.975,-15.2) 63(1.625,-15.2) 64(2.275,-15.2) 65(2.925,-15.2) 66(3.575,-15.2) 67(4.225,-15.2) 68(4.875,-15.2) 69(5.525,-15.2) 70(6.175,-15.2) 71(6.825,-15.2) 72(7.475,-15.2) 73(8.125,-15.2) 74(8.775,-15.2) 75(9.425,-15.2) 76(10.075,-15.2) 77(10.725,-15.2) 78(11.375,-15.2) 79(12.025,-15.2) 80(12.675,-15.2) 121(12.675,15.2) 122(12.025,15.2) 123(11.375,15.2) 124(10.725,15.2) 125(10.075,15.2) 126(9.425,15.2) 127(8.775,15.2) 128(8.125,15.2) 129(7.475,15.2) 130(6.825,15.2) 131(6.175,15.2) 132(5.525,15.2) 133(4.875,15.2) 134(4.225,15.2) 135(3.575,15.2) 136(2.925,15.2) 137(2.275,15.2) 138(1.625,15.2) 139(0.975,15.2) 140(0.325,15.2) 141(-0.325,15.2) 142(-0.975,15.2) 143(-1.625,15.2) 144(-2.275,15.2) 145(-2.925,15.2) 146(-3.575,15.2) 147(-4.225,15.2) 148(-4.875,15.2) 149(-5.525,15.2) 150(-6.175,15.2) 151(-6.825,15.2) 152(-7.475,15.2) 153(-8.125,15.2) 154(-8.775,15.2) 155(-9.425,15.2) 156(-10.075,15.2) 157(-10.725,15.2) 158(-11.375,15.2) 159(-12.025,15.2) 160(-12.675,15.2)
Top Overlay:
  circle w0.6: c-12.65,12.65 r0.3
  circle w0.25: c-15.2,13.45 r0.125
  lines w0.2: -13.65,-13.65 13.65,-13.65 13.65,13.65 -13.65,13.65 -13.65,-13.65
Mechanical 13:
  circle w0.1: c-13.1,13.1 r0.5
  lines w0.1: -14,-14 14,-14 14,14 -14,14 -14,-14
Mechanical 15:
  lines w0.1: -0.5,0 0.5,0 ; 0,-0.5 0,0.5 ; -16.8,-16.8 16.8,-16.8 16.8,16.8 -16.8,16.8 -16.8,-16.8
3D body: height 4.1, standoff 0, extent -14,-14 14,14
